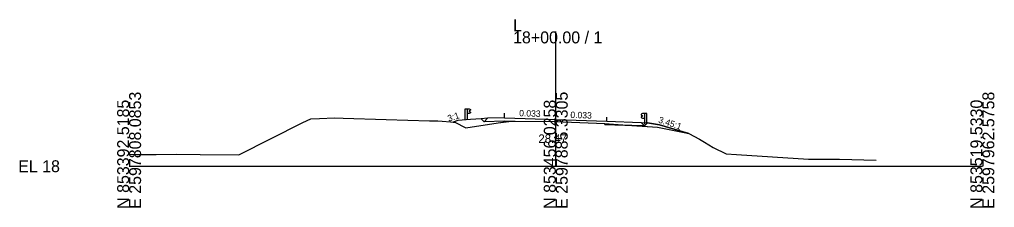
# Model space of a CAD drawing. Extents: x -26 to 1203, y -10 to 9526.
# Drawn here: x -25.7 to 202.8, y 7990.3 to 8034.4 of the extents above; entities that cross this region are included whole.
import ezdxf

# ---------------------------------------------------------------- set-up
doc = ezdxf.new("R2010")
doc.units = 0
for name, color, linetype in [('Exist Cross Section Cell', 7, 'Continuous'), ('Exist XS Center Line Elevation Label', 7, 'Continuous'), ('Exist XS Ground Line', 7, 'Continuous'), ('Prop XS Earthwork Shape', 7, 'Continuous'), ('Prop XS EOT Tick Mark', 7, 'Continuous'), ('Prop XS Finish Grade', 7, 'Continuous'), ('Prop XS Finish Grade Earthwork', 7, 'Continuous'), ('Prop XS Finish Grade Paved Shoulder', 7, 'Continuous'), ('Prop XS Finish Grade Pavement', 7, 'Continuous'), ('Prop XS Guardrail', 7, 'Continuous'), ('Prop XS Pvmt Edge Slope', 7, 'Continuous'), ('Prop XS SE Text', 7, 'Continuous'), ('Prop XS Side Slope Text', 7, 'Continuous'), ('Prop XS Subgrade Earthwork', 7, 'Continuous')]:
    doc.layers.add(name, color=color, linetype=linetype)

msp = doc.modelspace()

# ---------------------------------------------------------------- linework, layer by layer
at = {"layer": 'Exist Cross Section Cell'}
for p, q in [((100, 8000), (100, 8031.63)), ((0, 8000), (100, 8000)), ((100, 8000), (200, 8000))]:
    msp.add_line(p, q, dxfattribs=at)
at = {"layer": 'Exist XS Ground Line'}
for p, q in [((25.71, 8002.71), (40.75, 8010.23)), ((40.75, 8010.23), (42.59, 8011.15)), ((42.59, 8011.15), (44.59, 8011.21)), ((44.59, 8011.21), (48.14, 8011.32)), ((48.14, 8011.32), (50.14, 8011.27)), ((50.14, 8011.27), (60.25, 8010.98)), ((60.25, 8010.98), (70.37, 8010.68)), ((70.37, 8010.68), (72.37, 8010.63)), ((72.37, 8010.63), (76.37, 8010.31)), ((76.37, 8010.31), (78.94, 8009.02)), ((78.94, 8009.02), (86.54, 8010.15)), ((86.54, 8010.15), (89.23, 8010.54)), ((89.23, 8010.54), (90.45, 8010.54)), ((90.45, 8010.54), (100, 8010.47)), ((100, 8010.47), (100.49, 8010.47)), ((100.49, 8010.47), (101.71, 8010.42)), ((101.71, 8010.42), (111.51, 8009.99)), ((111.51, 8009.99), (115.66, 8009.7)), ((115.66, 8009.7), (123.82, 8009.14)), ((123.82, 8009.14), (129.69, 8007.97)), ((129.69, 8007.97), (131.21, 8007.7)), ((131.21, 8007.7), (133.73, 8006.33)), ((133.73, 8006.33), (134.9, 8005.61)), ((134.9, 8005.61), (136.93, 8004.39)), ((136.93, 8004.39), (139.94, 8002.91)), ((0, 8002.82), (1.73, 8002.77)), ((1.73, 8002.77), (6.34, 8002.78)), ((6.34, 8002.78), (11.16, 8002.8)), ((11.16, 8002.8), (16.68, 8002.72)), ((16.68, 8002.72), (25.71, 8002.71)), ((139.94, 8002.91), (142.38, 8002.75)), ((142.38, 8002.75), (159.24, 8001.69)), ((159.24, 8001.69), (166.54, 8001.67)), ((166.54, 8001.67), (175.14, 8001.4))]:
    msp.add_line(p, q, dxfattribs=at)
at = {"layer": 'Prop XS Earthwork Shape'}
for points in [[(89.03, 8010.52), (88, 8010.55), (83.19, 8010.45), (82.5, 8011.14), (80.02, 8010.94), (77.02, 8010.7), (75.93, 8010.34), (76.37, 8010.31), (78.94, 8009.02), (86.54, 8010.15)], [(89.03, 8010.52), (89.19, 8010.54), (89.19, 8010.51)], [(117.8, 8009.55), (123.82, 8009.14), (129.69, 8007.97), (131.21, 8007.7), (124.31, 8009.7), (121.51, 8010.15), (120.82, 8009.45)], [(111.48, 8009.99), (111.51, 8009.99), (115.66, 8009.7), (117.8, 8009.55), (111.48, 8009.76)]]:
    msp.add_lwpolyline(points, close=True, dxfattribs=at)
at = {"layer": 'Prop XS EOT Tick Mark'}
for p, q in [((88, 8011.46), (88, 8012.46)), ((88, 8011.34), (88, 8012.34)), ((112, 8010.54), (112, 8011.54))]:
    msp.add_line(p, q, dxfattribs=at)
at = {"layer": 'Prop XS Finish Grade'}
for p, q in [((84, 8011.26), (82.5, 8011.14)), ((120, 8010.27), (121.51, 8010.15))]:
    msp.add_line(p, q, dxfattribs=at)
at = {"layer": 'Prop XS Finish Grade Earthwork'}
for p, q in [((77.02, 8010.7), (75.93, 8010.34)), ((80.02, 8010.94), (77.02, 8010.7)), ((82.5, 8011.14), (80.02, 8010.94)), ((121.51, 8010.15), (124.31, 8009.7)), ((124.31, 8009.7), (131.21, 8007.7))]:
    msp.add_line(p, q, dxfattribs=at)
at = {"layer": 'Prop XS Finish Grade Paved Shoulder'}
msp.add_line((88, 8011.34), (84, 8011.26), dxfattribs=at)
at = {"layer": 'Prop XS Finish Grade Pavement'}
for p, q in [((88, 8011.34), (100, 8010.94)), ((100, 8010.94), (112, 8010.54)), ((112, 8010.54), (120, 8010.27))]:
    msp.add_line(p, q, dxfattribs=at)
at = {"layer": 'Prop XS Guardrail'}
for p, q in [((78.73, 8013.49), (79.23, 8013.49)), ((78.73, 8010.99), (78.73, 8013.49)), ((79.23, 8013.49), (79.73, 8013.49)), ((79.23, 8013.49), (79.23, 8010.99)), ((79.73, 8012.36), (79.23, 8012.36)), ((79.73, 8013.49), (80.02, 8013.29)), ((80.02, 8013.17), (79.73, 8012.97)), ((79.73, 8012.97), (79.73, 8012.88)), ((79.73, 8012.88), (80.02, 8012.68)), ((80.02, 8012.56), (79.73, 8012.36)), ((80.02, 8013.29), (80.05, 8013.23)), ((80.05, 8013.23), (80.02, 8013.17)), ((80.02, 8012.68), (80.05, 8012.62)), ((80.05, 8012.62), (80.02, 8012.56)), ((120.33, 8012.38), (120.04, 8012.18)), ((120.83, 8012.38), (120.33, 8012.38)), ((121.33, 8012.38), (120.83, 8012.38)), ((120.83, 8012.38), (120.83, 8009.84)), ((121.33, 8010.09), (121.33, 8012.38)), ((120.04, 8012.18), (120.01, 8012.12)), ((120.01, 8012.12), (120.04, 8012.06)), ((120.04, 8011.57), (120.01, 8011.51)), ((120.01, 8011.51), (120.04, 8011.45)), ((120.04, 8012.06), (120.33, 8011.86)), ((120.33, 8011.77), (120.04, 8011.57)), ((120.04, 8011.45), (120.33, 8011.25)), ((120.33, 8011.86), (120.33, 8011.77)), ((120.33, 8011.25), (120.83, 8011.25))]:
    msp.add_line(p, q, dxfattribs=at)
at = {"layer": 'Prop XS Pvmt Edge Slope'}
for p, q in [((84, 8011.26), (83.19, 8010.45)), ((120, 8010.27), (120.82, 8009.45))]:
    msp.add_line(p, q, dxfattribs=at)
at = {"layer": 'Prop XS Subgrade Earthwork'}
for p, q in [((83.19, 8010.45), (82.5, 8011.14)), ((88, 8010.55), (83.19, 8010.45)), ((89.19, 8010.51), (88, 8010.55)), ((89.19, 8010.54), (89.19, 8010.51)), ((120.82, 8009.45), (121.51, 8010.15)), ((111.48, 8009.76), (111.48, 8009.99)), ((111.48, 8009.76), (120.82, 8009.45))]:
    msp.add_line(p, q, dxfattribs=at)

# ---------------------------------------------------------------- texts
at = {"layer": 'Exist Cross Section Cell'}
for s, p in [('L', (90, 8031.63)), ('18+00.00 / 1', (90, 8028.83)), ('EL 18', (-26, 7998.6))]:
    msp.add_text(s, height=2.8, dxfattribs=at).set_placement(p)
for s, p in [('E 2597808.0853', (2.8, 7990)), ('E 2597885.3305', (102.8, 7990)), ('E 2597962.5758', (202.8, 7990)), ('N 853392.5185', (0, 7990)), ('N 853456.0258', (100, 7990)), ('N 853519.5330', (200, 7990))]:
    msp.add_text(s, height=2.8, rotation=90, dxfattribs=at).set_placement(p)
at = {"layer": 'Exist XS Center Line Elevation Label'}
msp.add_text('28.47', height=2, dxfattribs=at).set_placement((95.93, 8005.47))
at = {"layer": 'Prop XS SE Text'}
for p in [(91.41, 8011.73), (103.41, 8011.33)]:
    msp.add_text('0.033', height=1.5, rotation=358.0834, dxfattribs=at).set_placement(p)
at = {"layer": 'Prop XS Side Slope Text'}
for s, rotation, p in [('3:1', 18.4349, (74.91, 8010.43)), ('3.45:1', 341.5651, (123.92, 8010.27))]:
    msp.add_text(s, height=1.5, rotation=rotation, dxfattribs=at).set_placement(p)

doc.saveas('drawing.dxf')
